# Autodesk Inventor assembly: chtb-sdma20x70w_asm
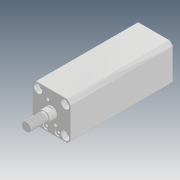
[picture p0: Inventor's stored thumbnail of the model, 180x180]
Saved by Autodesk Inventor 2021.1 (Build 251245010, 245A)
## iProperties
Company: Microsoft
Created: 2018-05
Part Number: chtb-sdma20x70w_asm
Description: STEP AP214
Document SubType Name: Assembly
Designer: user
Title: chtb-sdma20x70w_asm.STEP
Author: Windows
Revision Number: ÈÎºÎ
Sending System: SolidWorks 2015
Preprocessor: SwSTEP 2.0
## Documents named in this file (4)
- D:\Vault_2016\Projekty\Clamptek\Hydraulic\CHTB\CHTB-20\Inventor\CHTB-SDMA20x70W\chtb-sdma20x70w_asm.iam
- D:\Vault_2016\Projekty\Clamptek\Hydraulic\CHTB\CHTB-20\Inventor\CHTB-SDMA20x70W\CHTB-SDMA20X70NBT.ipt
- D:\Vault_2016\Projekty\Clamptek\Hydraulic\CHTB\CHTB-20\Inventor\CHTB-SDMA20x70W\CHTB-SDMA20X70WHSG.ipt
- D:\Vault_2016\Projekty\Clamptek\Hydraulic\CHTB\CHTB-20\Inventor\CHTB-SDMA20x70W\QG_3.ipt
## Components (3 placed, 3 different names)
1. CHTB-SDMA20X70NBT_1
2. CHTB-SDMA20X70WHSG_2
3. QG_3_3
